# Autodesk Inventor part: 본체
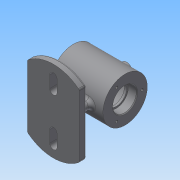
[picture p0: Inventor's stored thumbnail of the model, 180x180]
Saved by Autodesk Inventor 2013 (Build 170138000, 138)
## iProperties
Created: 2017-12
Part Number: 본체
Material: 일반
Document SubType Name: Modeling
Designer: Administrator
Density: 1 g/cm^3
Author: Administrator
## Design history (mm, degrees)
sketch "스케치1"
  geometry: L1 (-35, 0)-(35, 0); L2 (-35, 0)-(-35, 16); L3 (-35, 30)-(35, 30); L4 (35, 30)-(35, 16); L5 (-35, 16)-(-23, 16); L6 (-23, 16)-(-23, 14); L7 (-23, 14)-(-20, 14); L8 (-20, 14)-(-20, 25); L9 (-20, 25)-(20, 25); L10 (20, 25)-(20, 14); L11 (20, 14)-(23, 14); L12 (23, 14)-(23, 16); L13 (23, 16)-(35, 16); L14 (-35, 16)-(-35, 30); L15 (35, 16)-(35, 0); 3 further points
  constraints: 30 end point, 10 parallel, 9 perpendicular, 2 coincident, 2 midpoint, 1 horizontal, 1 vertical alignment
  dimensions: "d0" = 70 distance of L1.start L1.end; "d2" = 60 diameter of L3 L1; "d3" = 32 diameter of L13 L1; "d4" = 28 diameter of L11 L1; "d5" = 12 distance of L12.end L4.end; "d6" = 50 diameter of L9 L1; "d7" = 32 diameter of L5 L1; "d8" = 28 diameter of L7 L1; "d9" = 12 distance of L2.end L5.end; "d10" = 40 distance of L8.end L9.end
revolve "회전1" sketch "스케치1" stored, may be unused: angle "d11" = 90 deg
node "작업 평면1"
sketch "스케치2"
  geometry: L1 (-35, 42.426)-(-35, -42.426); L2 (35, 42.426)-(35, -42.426); L3 (-5, 40)-(-5, 24); L4 (5, 24)-(5, 40); L5 (-5, -40)-(-5, -24); L6 (5, -24)-(5, -40); L7 (-15, 5)-(15, 5); L8 (15, -5)-(-15, -5); A1 r 55 centre (0, 0) between (35, 42.426) and (-35, 42.426); A2 r 55 centre (0, 0) between (35, -42.426) and (35, 42.426); A3 r 55 centre (0, 0) between (-35, 42.426) and (-35, -42.426); A4 r 55 centre (0, 0) between (-35, -42.426) and (35, -42.426); A5 r 5 centre (0, 24) between (-5, 24) and (5, 24); A6 r 5 centre (0, 40) between (5, 40) and (-5, 40); A7 r 5 centre (0, -24) between (5, -24) and (-5, -24); A8 r 5 centre (0, -40) between (-5, -40) and (5, -40); A9 r 5 centre (15, 0) between (15, -5) and (15, 5); A10 r 5 centre (-15, 0) between (-15, 5) and (-15, -5); 1 further point
  constraints: 21 point on circle, 16 end point, 12 tangent, 10 centre point, 6 parallel, 2 vertical alignment, 1 coincident, 1 horizontal alignment, 1 perpendicular, 1 vertical
  dimensions: "d13" = 110 diameter of A1; "d14" = 70 distance between parallel lines of L1 L2; "d15" = 35 distance from line of point (0, 0) L2 (= 0.5 x d14); "d16" = 5 radius of A6; "d17" = 16 distance of A5.centre A6.centre; "d18" = 24 distance of point (0, 0) A5.centre; "d19" = 5 radius of A7; "d20" = 24 distance of point (0, 0) A7.centre; "d21" = 16 distance of A8.centre A7.centre; "d22" = 5 radius of A10; "d23" = 30 distance of A9.centre A10.centre; "d24" = 15 distance of A9.centre point (0, 0) (= 0.5 x d23)
extrude "돌출1" join sketch "스케치2" distance "d25" = 10; taper "d26" = 0 deg
extrude "돌출2" join sketch "스케치2" stored distance "d27" = 10; taper "d28" = 0 deg
sketch "스케치3"
  geometry: L1 (0, 0)-(0, 23); C1 r 16 at (0, 0) reference
  constraints: 2 end point, 1 vertical
  dimensions: "d29" = 23 distance of L1.start L1.end
hole "구멍1" sketch "스케치3" at (0, 23) diameter "d30" = 3.242; stored, may be unused: countersink angle "d34" = 90 deg, drill point angle "d36" = 118 deg; dims "d31" = 8, "d32" = 4, "d33" = 2, "d35" = 10
node "작업 평면2"
sketch "스케치4"
  geometry: C1 r 8 at (0, 0); 1 further point
  constraints: 1 centre point, 1 coincident
  dimensions: "d41" = 16 diameter of C1
extrude "돌출3" join sketch "스케치4" stored distance "d42" = 10; taper "d43" = 0 deg
sketch "스케치5"
  geometry: C1 r 8 at (0, 0) reference; C2 r 4 at (0, 0)
  constraints: 1 centre point, 1 coincident
  dimensions: "d44" = 8 diameter of C2
extrude "돌출4" cut sketch "스케치5" stored distance "d46" = 10; taper "d47" = 0 deg
fillet "모깎기2" dims "d49" = 3
fillet "모깎기4" dims "d51" = 5, "d53" = 3
chamfer "모따기1" distance "d54" = 1; stored, may be unused: second distance "d55" = 2, angle "d56" = 45 deg
fillet "모깎기6" dims "d57" = 3, "d58" = 0.3
node "작업 평면3"
sketch "스케치6"
  geometry: L1 (-35, 30)-(-35, -30) reference; L2 (35, 30)-(-35, 30) reference; 2 further points
  constraints: 1 other
  dimensions: "d60" = 35 distance from line of L1 point (0, 0); "d61" = 30 distance from line of L2 point (0, 0)
feature "엠보싱1" sketch "스케치6" dims "d0" = 70, "d2" = 60, "d3" = 32, "d4" = 28, "d5" = 12, "d6" = 50, "d7" = 32, "d8" = 28, "d9" = 12, "d10" = 40, "d62" = 0.5, "d63" = 0
node "솔리드1"
pattern_circular "원형 패턴1" dims angle "d38" = 360 deg
mirror "대칭1"
other parameters: "d12" = -62, "d40" = 37, "d59" = -46
